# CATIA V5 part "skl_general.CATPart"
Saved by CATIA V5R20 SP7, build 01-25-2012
Part number: skl_general
Publications: "Plan.1", "Point A", "Point D", "Point E", "Point F", "Point B/G", "Point C", "longueur AD et BC", "Hauteur F", "Longueur Y de F", "Hauteur E", "Longueur Y de E", "H", "Hauteur B", "Longueur Y de B"
Bounding box of the stored display mesh (mm): x 0 to 0, y -20 to 70, z 0 to 40
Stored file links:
  U:\IAO_bon\skl_general.CATPart
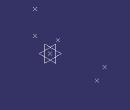
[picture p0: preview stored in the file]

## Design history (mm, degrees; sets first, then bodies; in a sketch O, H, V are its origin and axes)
Parameters
  `longueur AD et BC` = 0.06
  `Hauteur F` = 0.04
  `Longueur Y de F` = -0.02
  `Hauteur E` = 0.01
  `Longueur Y de E` = -0.02
  `Hauteur B` = 0.02
  `Longueur Y de B` = 0.01
Set1
  Plane1 "Plan Ref": type Offset, RefPlane yz-plane, Offset 0
  Point1 "Point A": type OnPlane, Support Plane1, H 0, V 0, Direction (0, 1, 0)
  Point2 "Point D": type OnPlane, Support Plane1, H 60 {= `longueur AD et BC`}, V 0, Direction (0, 1, 0)
  Point3 "Point E": type OnPlane, Support Plane1, H -20 {= `Longueur Y de E`}, V 10 {= `Hauteur E`}, Direction (0, 1, 0)
  Point4 "Point F": type OnPlane, Support Plane1, H -20 {= `Longueur Y de E`}, V 40 {= `Hauteur F`}, Direction (0, 1, 0)
  Point5 "Point B/G": type OnPlane, Support Plane1, H 10 {= `Longueur Y de B`}, V 20 {= `Hauteur B`}, Direction (0, 1, 0)
  Point6 "Point C": type OnPlane, Support Plane1, RefPoint Point5, H 60 {= `longueur AD et BC`}, V 0, Direction (0, 1, 0)
Body1 (main body)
